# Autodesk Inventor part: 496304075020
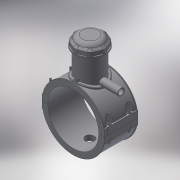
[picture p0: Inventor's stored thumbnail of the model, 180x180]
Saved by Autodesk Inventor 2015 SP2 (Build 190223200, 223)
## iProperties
Created: 2017-07
Part Number: 496304075020
Material: Generic
Description: PLASSON TAPPING SADDLE 75x20
Document SubType Name: Modeling
Designer: KIM
Mass: 653.905 g
Surface Area: 1579.88 cm^2
Volume: 653.905 cm^3
Density: 1 g/cm^3
Appearance: Default
Author: KIM
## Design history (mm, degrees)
derived "496304.ipt"
feature "Solid1::496304.ipt"
feature "Solid2::496304.ipt"
feature "Solid4::496304.ipt"
feature "Solid5::496304.ipt"
tag "TaggingFeature1"
body "Solid1"
body "Solid2"
other parameters: "d0" = 75, "d2" = 117, "d3" = 18.75, "d4" = 118, "d5" = 0, "d6" = 0.1, "d8" = 0, "d19" = 6, "d20" = 6, "d21" = 70.8, "d23" = 0, "d24" = 35.4, "d26" = 0, "d29" = 3, "d30" = 25, "d31" = 6, "d32" = 0, "d33" = 0, "d34" = 0.6, "d40" = 50.7, "d41" = 67.5, "d43" = 0, "d45" = 0, "d47" = 119.55, "d70" = 15, "d72" = 0, "d73" = 6, "d75" = 5, "d76" = 0, "d77" = 3.75, "d78" = 67.5, "d79" = 15, "d80" = 47.2, "d82" = 5 deg, "d84" = 4, "d85" = 14, "d86" = 0, "d87" = 3, "d88" = 0, "d89" = 1, "d90" = 1, "d91" = 94.4, "d92" = 0, "d93" = 0.5, "d94" = 39.47368, "d96" = 99.45, "d97" = 2.36, "d98" = 0, "d102" = 0.75, "d120" = 140 deg, "d121" = 24.228, "d122" = 20 deg, "d123" = 195, "d124" = 58.5, "d126" = 0, "d143" = 77.25, "d145" = 17.30769, "d149" = 1.125, "d150" = 19.03846, "d153" = 118, "d154" = 0, "d156" = 48.75, "d157" = 160 deg, "d159" = 4.5, "d161" = 1.125, "d162" = 70.8, "d163" = 0, "d164" = 37.5, "d167" = 7.5, "d168" = 47.56098, "d170" = 3.375, "d172" = 0, "d173" = 1, "d175" = 37.5, "d176" = 20 deg, "d177" = 5.25, "d178" = 22.5, "d180" = 0, "d183" = 9, "d184" = 4.2, "d185" = 38.35, "d186" = 38.35, "d187" = 48.75, "d188" = 6.75, "d189" = 5.25, "d190" = 0, "d191" = 73.125, "d193" = 6.3, "d194" = 4.13, "d195" = 90 deg, "d197" = 0, "d199" = 0, "d200" = 11.25, "d202" = 0, "d203" = 177, "d204" = 64.125, "d205" = 47.25, "d206" = 57.375, "d207" = 132.75, "d208" = 138.06, "d209" = 164.61, "d210" = 58.05, "d211" = 67.5, "d212" = 54, "d213" = 36, "d216" = 0, "d217" = 7.5, "d218" = 7.5, "d219" = 1.5, "d222" = 75, "d224" = 0, "d230" = 4.5, "d233" = 6, "d236" = 58.5, "d237" = 35.4, "d238" = 6.02433, "d240" = 35.4, "d241" = 35.4, "d242" = 35.4, "d243" = 6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
